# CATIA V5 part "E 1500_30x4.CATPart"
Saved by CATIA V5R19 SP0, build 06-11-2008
Definition: E 1500_30x4
Nomenclature: E 1500_30x4
Description: PART--DESC
Material "Steel": density 7860 kg/m3, Young's modulus 2e+11 Pa, Poisson ratio 0.266, thermal expansion 1.17e-05 1/K
Bounding box of the stored display mesh (mm): x -319 to -289, y -190 to -160, z -278 to -274
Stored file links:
  G:\UTB\Kombinované\Bakalářská práce\Catia\FORMA\E 1500_30x4.CATPart
  D:\Aplikace\CATIA\Nová složka\win_b64\startup\materials\Catalog.CATMaterial
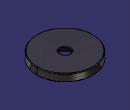
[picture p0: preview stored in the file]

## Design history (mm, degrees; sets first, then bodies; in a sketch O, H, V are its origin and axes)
Body1 "E 1500_30x4" (main body)
  Solid1: solid without history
